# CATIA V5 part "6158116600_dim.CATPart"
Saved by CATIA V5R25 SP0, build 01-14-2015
Part number: 6158116600_dim
Source: made
Property "PROI_CREATED_ON": "12/17/2008 9:21:37 AM"
Property "BLANK_DRAWING": "--"
Property "DRAWN_BY": "API"
Property "FINISH": "--"
Property "HEAT_TREATMENT": "ASSIGN"
Property "MATERIAL": "ASSIGN"
Property "PROJECT": "--"
Property "PROTOTYPE_NO": "--"
Property "RELATED_DRAWING": "--"
Property "COMPLETE_MATERIAL": "ASSIGN-ASSIGN"
Property "DESCRIPTION": "6158116600_DIM"
Property "DRAWING_EXIST": "--"
Property "MANUFACTURER": "--"
Property "MANUFACTURER_2": "--"
Property "MANUFACTURER_REF": "--"
Property "TYPE_PART": "--"
Property "TODAY_DATE": "2021/11/09"
Property "PDMREV": "01.0"
Property "PDMRL": "Technical Support"
Property "PROI_REVISION": "01"
Property "PROI_VERSION": "0"
Property "PROI_RELEASE": "Technical Support"
Property "PTC_MODIFIED": false
Property "MFG_WP_MATERIAL": "ASSIGN"
Property "COMPANY_CODE": "---"
Property "DESCRIPTION_JP": "6158116600_"
Property "PQP_DOCUMENT": "--"
Property "GHOST": false
Property "NO_PART": false
Property "PTC_WM_ITERATION": "0"
Property "PTC_WM_VERSION": "01.0"
Property "PTC_WM_CREATED_ON": "09-Nov-21 09:42:00 AM"
Property "PTC_WM_MODIFIED_ON": "09-Nov-21 09:42:00 AM"
Property "PTC_WM_NAME": "6158116600_dim.prt"
Property "PTC_WM_NUMBER": "6158116600_DIM.PRT"
Property "PTC_WM_LIFECYCLE_STATE": "Technical Support"
Property "PTC_WM_LIFECYCLE": "Design_Process"
Property "PTC_WM_REVISION": "01"
Property "PTC_WM_CREATED_BY": "Alexis Picaud (Greextap) (Greextap: CPD)"
Property "PTC_WM_MODIFIED_BY": "Alexis Picaud (Greextap) (Greextap: CPD)"
Property "PTC_ORGANIZATION_ID": "CPD"
Property "PTC_WM_LOCATION": "/Products/ACCESSORIES/A1020-D53 TORQUE ARM/9-01-Dimensional Drawings and 3D"
Property "PTC_WM_PART_NAME": "6158116600_dim.prt"
Property "PTC_WM_PART_NUMBER": "6158116600_DIM"
Property "PTC_WM_TEAM": "Default"
Property "EXPORT_CONTROL": "NULL"
Property "PTC_COMMON_NAME": "6158116600_dim.prt"
Property "PTC_MASTER_MATERIAL": "ASSIGN"
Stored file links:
  d:\ptc\Echange\temp\6158116600_dim.CATPart

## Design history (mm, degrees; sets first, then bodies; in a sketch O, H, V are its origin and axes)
AxisSystem1 "CS0": origin (0, 0, 0), X (1, 0, 0), Y (0, 1, 0), Z (0, 0, 1)
Set1
  DatumSurface1 "Sheet.1"
  DatumSurface2 "Sheet.2"
  DatumSurface3 "Sheet.3"
  DatumSurface4 "Sheet.4"
  DatumSurface5 "Sheet.5"
  DatumSurface6 "Sheet.6"
  DatumSurface7 "Sheet.7"
  DatumSurface8 "Sheet.8"
  DatumSurface9 "Sheet.9"
  DatumSurface10 "Sheet.10"
  DatumSurface11 "Sheet.11"
  DatumSurface12 "Sheet.12"
  DatumSurface13 "Sheet.13"
  DatumSurface14 "Sheet.14"
  DatumSurface15 "Sheet.15"
  DatumSurface16 "Sheet.16"
  DatumSurface17 "Sheet.17"
  DatumSurface18 "Sheet.18"
  DatumSurface19 "Sheet.19"
  DatumSurface20 "Sheet.20"
  DatumSurface21 "Sheet.21"
  DatumSurface22 "Sheet.22"
  DatumSurface23 "Sheet.23"
  DatumSurface24 "Sheet.24"
  DatumSurface25 "Sheet.25"
  DatumSurface26 "Sheet.26"
  DatumSurface27 "Sheet.27"
  DatumSurface28 "Sheet.28"
  DatumSurface29 "Sheet.29"
  DatumSurface30 "Sheet.30"
  DatumSurface31 "Sheet.31"
  DatumSurface32 "Sheet.32"
  DatumSurface33 "Sheet.33"
  DatumSurface34 "Sheet.34"
  DatumSurface35 "Sheet.35"
  DatumSurface36 "Sheet.36"
  DatumSurface37 "Sheet.37"
  DatumSurface38 "Sheet.38"
  DatumSurface39 "Sheet.39"
  DatumSurface40 "Sheet.40"
  DatumSurface41 "Sheet.41"
  DatumSurface42 "Sheet.42"
  DatumSurface43 "Sheet.43"
  DatumSurface44 "Sheet.44"
  DatumSurface45 "Sheet.45"
  DatumSurface46 "Sheet.46"
  DatumSurface47 "Sheet.47"
  DatumSurface48 "Sheet.48"
  DatumSurface49 "Sheet.49"
  DatumSurface50 "Sheet.50"
  DatumSurface51 "Sheet.51"
  DatumSurface52 "Sheet.52"
  DatumSurface53 "Sheet.53"
  DatumSurface54 "Sheet.54"
  DatumSurface55 "Sheet.55"
  DatumSurface56 "Sheet.56"
  DatumSurface57 "Sheet.57"
  DatumSurface58 "Sheet.58"
  DatumSurface59 "Sheet.59"
  DatumSurface60 "Sheet.60"
  DatumSurface61 "Sheet.61"
  DatumSurface62 "Sheet.62"
  DatumSurface63 "Sheet.63"
  DatumSurface64 "Sheet.64"
  DatumSurface65 "Sheet.65"
  DatumSurface66 "Sheet.66"
  DatumSurface67 "Sheet.67"
  DatumSurface68 "Sheet.68"
  DatumSurface69 "Sheet.69"
  DatumSurface70 "Sheet.70"
  DatumSurface71 "Sheet.71"
  DatumSurface72 "Sheet.72"
  DatumSurface73 "Sheet.73"
  DatumSurface74 "Sheet.74"
  DatumSurface75 "Sheet.75"
  DatumSurface76 "Sheet.76"
  DatumSurface77 "Sheet.77"
  DatumSurface78 "Sheet.78"
  DatumSurface79 "Sheet.79"
  DatumSurface80 "Sheet.80"
  DatumSurface81 "Sheet.81"
  DatumSurface82 "Sheet.82"
  DatumSurface83 "Sheet.83"
  DatumSurface84 "Sheet.84"
  DatumSurface85 "Sheet.85"
  DatumSurface86 "Sheet.86"
  DatumSurface87 "Sheet.87"
  DatumSurface88 "Sheet.88"
  DatumSurface89 "Sheet.89"
  DatumSurface90 "Sheet.90"
  DatumSurface91 "Sheet.91"
  DatumSurface92 "Sheet.92"
  DatumSurface93 "Sheet.93"
  DatumSurface94 "Sheet.94"
  DatumSurface95 "Sheet.95"
  DatumSurface96 "Sheet.96"
  DatumSurface97 "Sheet.97"
  DatumSurface98 "Sheet.98"
  DatumSurface99 "Sheet.99"
  DatumSurface100 "Sheet.100"
  DatumSurface101 "Sheet.101"
  DatumSurface102 "Sheet.102"
  DatumSurface103 "Sheet.103"
  DatumSurface104 "Sheet.104"
  DatumSurface105 "Sheet.105"
  DatumSurface106 "Sheet.106"
  DatumSurface107 "Sheet.107"
  DatumSurface108 "Sheet.108"
  DatumSurface109 "Sheet.109"
  DatumSurface110 "Sheet.110"
  DatumSurface111 "Sheet.111"
  DatumSurface112 "Sheet.112"
  DatumSurface113 "Sheet.113"
  DatumSurface114 "Sheet.114"
  Plane1 "RIGHT": stored without definition
  Plane2 "TOP": stored without definition
  Plane3 "FRONT": stored without definition
Body1 "PartBody" (main body)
